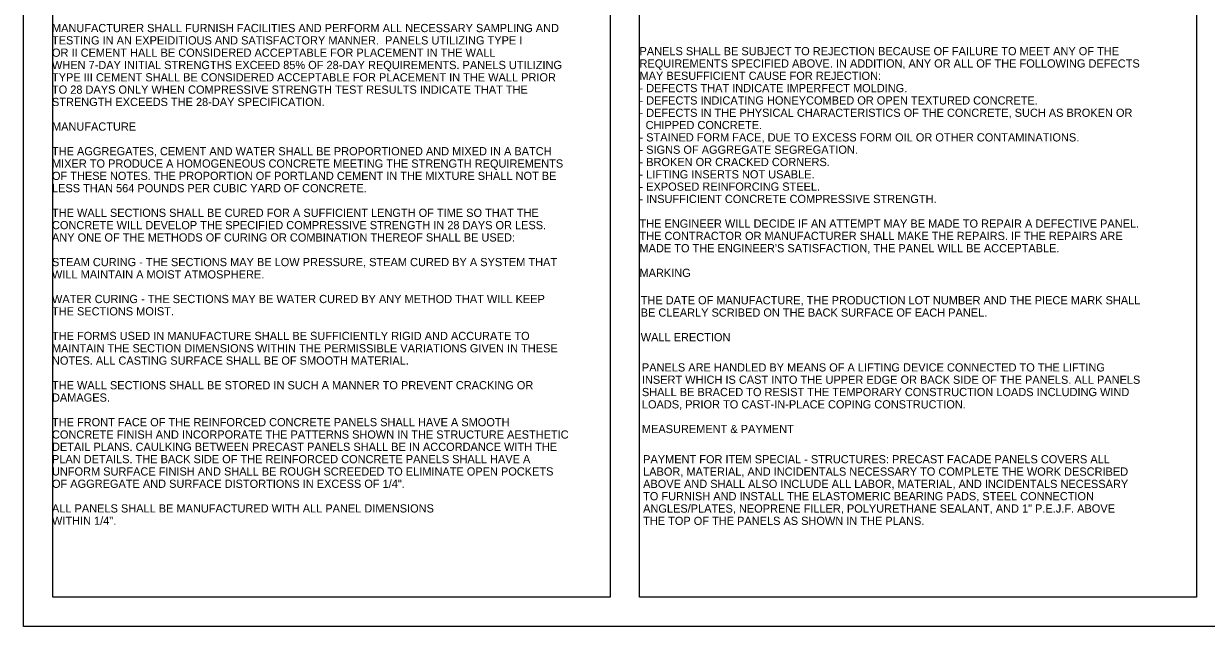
# Model space of a CAD drawing. Extents: x -27.4 to 41.5, y -43.2 to 24.4.
# Drawn here: x 1.24 to 21.41, y -22.74 to -12.47 of the extents above; entities that cross this region are included whole.
import ezdxf

# ---------------------------------------------------------------- set-up
doc = ezdxf.new("R2010")
doc.units = 0
for name, color, linetype in [('BR_P_Slab_Object', 7, 'Continuous'), ('BR_P_Sub_Foot_Hidden', 7, 'Continuous'), ('SH_Data', 7, 'Continuous')]:
    doc.layers.add(name, color=color, linetype=linetype)

msp = doc.modelspace()

# ---------------------------------------------------------------- linework, layer by layer
at = {"layer": 'BR_P_Slab_Object'}
for points in [[(1.744, -2.241), (11.244, -2.241), (11.244, -22.241), (1.744, -22.241)], [(11.744, -2.241), (21.244, -2.241), (21.244, -22.241), (11.744, -22.241)]]:
    msp.add_lwpolyline(points, close=True, dxfattribs=at)
at = {"layer": 'SH_Data'}
msp.add_lwpolyline([(1.244, -1.741), (31.744, -1.741), (31.744, -22.741), (1.244, -22.741)], close=True, dxfattribs=at)

# ---------------------------------------------------------------- texts
at = {"layer": 'BR_P_Sub_Foot_Hidden'}
for s, p in [('MANUFACTURER SHALL FURNISH FACILITIES AND PERFORM ALL NECESSARY SAMPLING AND', (1.727, -12.61)), ('TESTING IN AN EXPEIDITIOUS AND SATISFACTORY MANNER.  PANELS UTILIZING TYPE I', (1.727, -12.82)), ('OR II CEMENT HALL BE CONSIDERED ACCEPTABLE FOR PLACEMENT IN THE WALL', (1.727, -13.03)), ('PANELS SHALL BE SUBJECT TO REJECTION BECAUSE OF FAILURE TO MEET ANY OF THE', (11.745, -13.004)), ('WHEN 7-DAY INITIAL STRENGTHS EXCEED 85% OF 28-DAY REQUIREMENTS. PANELS UTILIZING', (1.727, -13.24)), ('REQUIREMENTS SPECIFIED ABOVE. IN ADDITION, ANY OR ALL OF THE FOLLOWING DEFECTS', (11.745, -13.214)), ('TYPE III CEMENT SHALL BE CONSIDERED ACCEPTABLE FOR PLACEMENT IN THE WALL PRIOR', (1.727, -13.45)), ('MAY BESUFFICIENT CAUSE FOR REJECTION:', (11.745, -13.424)), ('- DEFECTS THAT INDICATE IMPERFECT MOLDING.', (11.745, -13.634)), ('TO 28 DAYS ONLY WHEN COMPRESSIVE STRENGTH TEST RESULTS INDICATE THAT THE', (1.727, -13.66)), ('- DEFECTS INDICATING HONEYCOMBED OR OPEN TEXTURED CONCRETE.', (11.745, -13.844)), ('STRENGTH EXCEEDS THE 28-DAY SPECIFICATION.', (1.727, -13.87)), ('- DEFECTS IN THE PHYSICAL CHARACTERISTICS OF THE CONCRETE, SUCH AS BROKEN OR', (11.745, -14.054)), ('MANUFACTURE', (1.727, -14.29)), ('  CHIPPED CONCRETE.', (11.745, -14.264)), ('- STAINED FORM FACE, DUE TO EXCESS FORM OIL OR OTHER CONTAMINATIONS.', (11.745, -14.474)), ('THE AGGREGATES, CEMENT AND WATER SHALL BE PROPORTIONED AND MIXED IN A BATCH', (1.727, -14.71)), ('- SIGNS OF AGGREGATE SEGREGATION.', (11.745, -14.684)), ('MIXER TO PRODUCE A HOMOGENEOUS CONCRETE MEETING THE STRENGTH REQUIREMENTS', (1.727, -14.92)), ('- BROKEN OR CRACKED CORNERS.', (11.745, -14.894)), ('OF THESE NOTES. THE PROPORTION OF PORTLAND CEMENT IN THE MIXTURE SHALL NOT BE', (1.727, -15.13)), ('- LIFTING INSERTS NOT USABLE.', (11.745, -15.104)), ('LESS THAN 564 POUNDS PER CUBIC YARD OF CONCRETE.', (1.727, -15.34)), ('- EXPOSED REINFORCING STEEL.', (11.745, -15.314)), ('- INSUFFICIENT CONCRETE COMPRESSIVE STRENGTH.', (11.745, -15.524)), ('THE WALL SECTIONS SHALL BE CURED FOR A SUFFICIENT LENGTH OF TIME SO THAT THE', (1.727, -15.76)), ('CONCRETE WILL DEVELOP THE SPECIFIED COMPRESSIVE STRENGTH IN 28 DAYS OR LESS.', (1.727, -15.97)), ('THE ENGINEER WILL DECIDE IF AN ATTEMPT MAY BE MADE TO REPAIR A DEFECTIVE PANEL.', (11.745, -15.944)), ('ANY ONE OF THE METHODS OF CURING OR COMBINATION THEREOF SHALL BE USED:', (1.727, -16.18)), ('THE CONTRACTOR OR MANUFACTURER SHALL MAKE THE REPAIRS. IF THE REPAIRS ARE', (11.745, -16.154)), ("MADE TO THE ENGINEER'S SATISFACTION, THE PANEL WILL BE ACCEPTABLE.", (11.745, -16.364)), ('STEAM CURING - THE SECTIONS MAY BE LOW PRESSURE, STEAM CURED BY A SYSTEM THAT', (1.727, -16.6)), ('WILL MAINTAIN A MOIST ATMOSPHERE.', (1.727, -16.81)), ('MARKING', (11.745, -16.784)), ('WATER CURING - THE SECTIONS MAY BE WATER CURED BY ANY METHOD THAT WILL KEEP', (1.727, -17.23)), ('THE DATE OF MANUFACTURE, THE PRODUCTION LOT NUMBER AND THE PIECE MARK SHALL', (11.766, -17.251)), ('THE SECTIONS MOIST.', (1.727, -17.44)), ('BE CLEARLY SCRIBED ON THE BACK SURFACE OF EACH PANEL.', (11.766, -17.461)), ('THE FORMS USED IN MANUFACTURE SHALL BE SUFFICIENTLY RIGID AND ACCURATE TO', (1.727, -17.86)), ('WALL ERECTION', (11.766, -17.881)), ('MAINTAIN THE SECTION DIMENSIONS WITHIN THE PERMISSIBLE VARIATIONS GIVEN IN THESE', (1.727, -18.07)), ('NOTES. ALL CASTING SURFACE SHALL BE OF SMOOTH MATERIAL.', (1.727, -18.28)), ('PANELS ARE HANDLED BY MEANS OF A LIFTING DEVICE CONNECTED TO THE LIFTING', (11.786, -18.396)), ('INSERT WHICH IS CAST INTO THE UPPER EDGE OR BACK SIDE OF THE PANELS. ALL PANELS', (11.786, -18.606)), ('THE WALL SECTIONS SHALL BE STORED IN SUCH A MANNER TO PREVENT CRACKING OR', (1.727, -18.7)), ('SHALL BE BRACED TO RESIST THE TEMPORARY CONSTRUCTION LOADS INCLUDING WIND', (11.786, -18.816)), ('DAMAGES.', (1.727, -18.91)), ('LOADS, PRIOR TO CAST-IN-PLACE COPING CONSTRUCTION.', (11.786, -19.026)), ('THE FRONT FACE OF THE REINFORCED CONCRETE PANELS SHALL HAVE A SMOOTH', (1.727, -19.33)), ('MEASUREMENT & PAYMENT', (11.786, -19.446)), ('CONCRETE FINISH AND INCORPORATE THE PATTERNS SHOWN IN THE STRUCTURE AESTHETIC', (1.727, -19.54)), ('DETAIL PLANS. CAULKING BETWEEN PRECAST PANELS SHALL BE IN ACCORDANCE WITH THE', (1.727, -19.75)), ('PLAN DETAILS. THE BACK SIDE OF THE REINFORCED CONCRETE PANELS SHALL HAVE A', (1.727, -19.96)), ('PAYMENT FOR ITEM SPECIAL - STRUCTURES: PRECAST FACADE PANELS COVERS ALL', (11.807, -19.962)), ('UNFORM SURFACE FINISH AND SHALL BE ROUGH SCREEDED TO ELIMINATE OPEN POCKETS', (1.727, -20.17)), ('LABOR, MATERIAL, AND INCIDENTALS NECESSARY TO COMPLETE THE WORK DESCRIBED', (11.807, -20.172)), ('OF AGGREGATE AND SURFACE DISTORTIONS IN EXCESS OF 1/4".', (1.727, -20.38)), ('ABOVE AND SHALL ALSO INCLUDE ALL LABOR, MATERIAL, AND INCIDENTALS NECESSARY', (11.807, -20.382)), ('TO FURNISH AND INSTALL THE ELASTOMERIC BEARING PADS, STEEL CONNECTION', (11.807, -20.592)), ('ALL PANELS SHALL BE MANUFACTURED WITH ALL PANEL DIMENSIONS', (1.727, -20.8)), ('ANGLES/PLATES, NEOPRENE FILLER, POLYURETHANE SEALANT, AND 1" P.E.J.F. ABOVE', (11.807, -20.802)), ('WITHIN 1/4".', (1.727, -21.01)), ('THE TOP OF THE PANELS AS SHOWN IN THE PLANS.', (11.807, -21.012))]:
    msp.add_text(s, height=0.14, dxfattribs=at).set_placement(p)

doc.saveas('drawing.dxf')
